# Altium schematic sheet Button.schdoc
size 297 x 209 mm; Symbol: Drawing-Symbol_A4; @Project Name: Hưhwwuey; @Page Count: 6; @Update Date: 2026-10-18; @Create Date: 2026-10-18; @Schematic Name: Schematic1; @Page No: 6; @Page Name: P1; Company: EasyEDA.com; Version: V1.0; Page Size: A4; Device: Drawing-Symbol_A4; @Create Time: 11:19:59; @Update Time: 11:19:59; Border: 1; Width: 1170; Height: 825; Region Start: 1; X Region Count: 6; Y Region Count: 4; Blade Width: 10; Title Block Position: 3; @Board Name: Board1
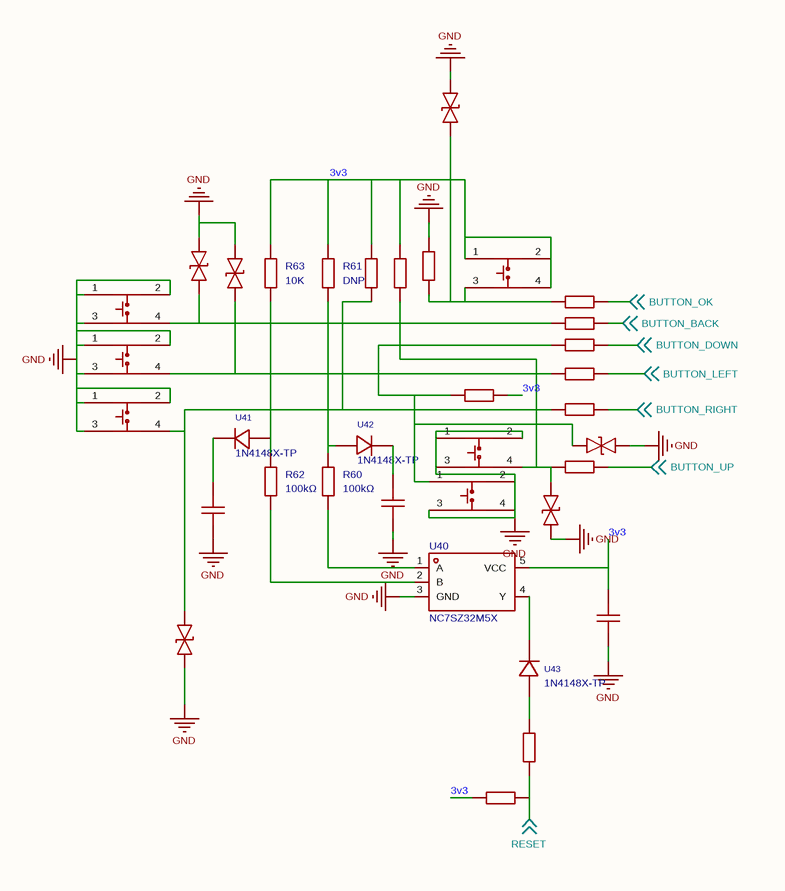
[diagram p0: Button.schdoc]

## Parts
C87  10uF  [C0603]  (value not drawn)
C88  10uF  [C0603]  (value not drawn)
C89  100nF  [C0402]  (value not drawn)
D9  ESD241B1W0201E6327XTSA1  [WLL-2-3_L0.6-W0.3-P0.36-BI]  (value not drawn)
D10  ESD241B1W0201E6327XTSA1  [WLL-2-3_L0.6-W0.3-P0.36-BI]  (value not drawn)
D11  ESD241B1W0201E6327XTSA1  [WLL-2-3_L0.6-W0.3-P0.36-BI]  (value not drawn)
D12  ESD241B1W0201E6327XTSA1  [WLL-2-3_L0.6-W0.3-P0.36-BI]  (value not drawn)
D13  ESD241B1W0201E6327XTSA1  [WLL-2-3_L0.6-W0.3-P0.36-BI]  (value not drawn)
D14  ESD241B1W0201E6327XTSA1  [WLL-2-3_L0.6-W0.3-P0.36-BI]  (value not drawn)
R60  100kΩ  [R0402]
R61  DNP  [R0402]
R62  100kΩ  [R0402]
R63  10K  [R0402]
R64  510Ω  [R0402]  (value not drawn)
R65  10K  [R0402]  (value not drawn)
R66  330Ω  [R0402]  (value not drawn)
R67  330Ω  [R0402]  (value not drawn)
R68  330Ω  [R0402]  (value not drawn)
R69  10K  [R0402]  (value not drawn)
R70  330Ω  [R0402]  (value not drawn)
R71  10K  [R0402]  (value not drawn)
R72  330Ω  [R0402]  (value not drawn)
R73  10K  [R0402]  (value not drawn)
R74  330Ω  [R0402]  (value not drawn)
R75  10K  [R0402]  (value not drawn)
SW1  SKRMAAE010  [SW-SMD_4P-L4.5-W4.5-P3.30-S3.75]  (value not drawn)
SW2  SKRMAAE010  [SW-SMD_4P-L4.5-W4.5-P3.30-S3.75]  (value not drawn)
SW3  SKRMAAE010  [SW-SMD_4P-L4.5-W4.5-P3.30-S3.75]  (value not drawn)
SW4  SKRMAAE010  [SW-SMD_4P-L4.5-W4.5-P3.30-S3.75]  (value not drawn)
SW5  SKRMAAE010  [SW-SMD_4P-L4.5-W4.5-P3.30-S3.75]  (value not drawn)
SW6  SKRMAAE010  [SW-SMD_4P-L4.5-W4.5-P3.30-S3.75]  (value not drawn)
U40  NC7SZ32M5X  [SOT-23-5_L2.9-W1.6-P0.95-LS2.8-BR]
U41  1N4148X-TP  [SOD-523F_L1.2-W0.8-LS1.7-RD]
U42  1N4148X-TP  [SOD-523F_L1.2-W0.8-LS1.7-RD]
U43  1N4148X-TP  [SOD-523F_L1.2-W0.8-LS1.7-RD]

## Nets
GND: C87.1 C88.1 C89.2 D9.2 D10.2 D11.1 D12.2 D13.1 D14.1 R71.2 SW1.1 SW1.2 SW1.3 SW2.1 SW2.2 SW2.3 SW3.1 SW3.2 SW3.3 SW5.1 SW5.2 SW5.3 SW6.2 SW6.3 SW6.4 U40.3(GND)
3v3: C89.1 R61.2 R63.2 R65.1 R69.2 R73.2 R75.2 SW4.1 SW4.2 SW4.4 U40.5(VCC)
BUTTON_BACK: R66.2 ; off-sheet BUTTON_BACK
BUTTON_DOWN: R74.2 ; off-sheet BUTTON_DOWN
BUTTON_LEFT: R67.2 ; off-sheet BUTTON_LEFT
BUTTON_OK: R70.2 ; off-sheet BUTTON_OK
BUTTON_RIGHT: R68.2 ; off-sheet BUTTON_RIGHT
BUTTON_UP: R72.2 ; off-sheet BUTTON_UP
RESET: R64.1 R65.2 ; off-sheet RESET
NetC87_2: C87.2 U41.1(C)
NetC88_2: C88.2 U42.1(C)
NetD9_1: D9.1 R60.2 R61.1 R66.1 SW1.4 U42.2(A)
NetD10_1: D10.1 R62.2 R63.1 R67.1 SW2.4 U41.2(A)
NetD11_2: D11.2 R68.1 R69.1 SW3.4
NetD12_1: D12.1 R70.1 R71.1 SW4.3
NetD13_2: D13.2 R72.1 R73.1 SW5.4
NetD14_2: D14.2 R74.1 R75.1 SW6.1
NetR60_1: R60.1 U40.1(A)
NetR62_1: R62.1 U40.2(B)
NetR64_2: R64.2 U43.2(A)
NetU40_4: U40.4(Y) U43.1(C)

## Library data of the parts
C87 C88 = CL10A106KP8NNNC: Capacitance:10uF Tolerance:±10% Tolerance:±10% Voltage Rating:10V Temperature Coefficient:X5R; Manufacturer: SAMSUNG(三星); 3D Model: 624118aa3cc7497086c383c2d72e08520819f05c4eef4c71ace90d822a990e87; 3D Model Transform: 62.992,31.496,0,0,0,0,0,0,0; Tolerance: ±10%; Voltage Rating: 10V; Temperature Coefficient: X5R; AddInBom: yes; ModelName: C0603_L1.6-W0.8-H0.8
C89 = CAP_0402: Symbol: CAP_OLD; 3D Model: b7d13df3e9464d7a99d0651d1a5b4d570819f05c4eef4c71ace90d822a990e87; 3D Model Transform: 39.37,19.685,0,0,0,0,0,0,0; ConvertToPcb: yes; ModelName: C0402_L1.0-W0.5-H0.5
D9-D14 = ESD241B1W0201E6327XTSA1: Polarity:Bidirectional Reverse Stand-Off Voltage (Vrwm):3.3V Clamping Voltage:6V Peak Pulse Current (Ipp):4.5A@8/20us Peak Pulse Power Dissipation (Ppp):25W Reverse Leakage Current (Ir):1nA Number of Channels:1 Operating Temperature:-55℃~+125℃ Operating T; Manufacturer: Infineon(英飞凌); AddInBom: yes; ModelId: cb6ec831a54246eaa6879a507ceff6700819f05c4eef4c71ace90d822a990e87; ModelTransform: 22.8346,11.0236,0,0,0,0,0,0,0; Reverse Stand-Off Voltage (Vrwm): 3.3V; Clamping Voltage: 6V; Peak Pulse Power Dissipation (Ppp): 25W; Reverse Leakage Current (Ir): 1nA; Number of Channels: 1; level of protection: IEC 61000-4-4；IEC 61000-4-5；IEC 61000-4-2; Type: TVS; Junction Capacitance: 6.5pF
R60 R62 = RC-02W104JT: Type:Thick Film Resistor Resistance:100kΩ Tolerance:±5% Tolerance:±5% Power(Watts):62.5mW Voltage-Supply(Max):50V Temperature Coefficient:±200ppm/℃ Temperature Coefficient:±200ppm/℃ Operating Temperature:-55℃~+155℃ Operating Temperature:-55℃~+155℃; Manufacturer: FH(风华); AddInBom: yes; ModelId: efdecb7dae4442949d28eecaf748420f0819f05c4eef4c71ace90d822a990e87; ModelName: R0402_L1.0-W0.5-H0.4; ModelTransform: 39.37,19.685,0,0,0,0,0,0,0; Tolerance: ±5%; Power(Watts): 62.5mW; Voltage-Supply(Max): 50V
R61 = Res_0402: Symbol: Res; 3D Model: efdecb7dae4442949d28eecaf748420f0819f05c4eef4c71ace90d822a990e87; 3D Model Transform: 39.37,19.685,0,0,0,0,0,0,0; Add into BOM: no; ConvertToPcb: yes; ModelName: R0402_L1.0-W0.5-H0.4
R63 R65 R69 R71 R73 R75 = Res_0402: Symbol: Res; 3D Model: efdecb7dae4442949d28eecaf748420f0819f05c4eef4c71ace90d822a990e87; 3D Model Transform: 39.37,19.685,0,0,0,0,0,0,0; ConvertToPcb: yes; ModelName: R0402_L1.0-W0.5-H0.4
R64 = RTT02511JTH: Type:Thick Film Resistor Resistance:510Ω Tolerance:±5% Tolerance:±5% Power(Watts):62.5mW Voltage-Supply(Max):50V Temperature Coefficient:±100ppm/℃ Temperature Coefficient:±100ppm/℃ Operating Temperature:-55℃~+155℃ Operating Temperature:-55℃~+155℃; Manufacturer: RALEC(旺诠); AddInBom: yes; ModelId: efdecb7dae4442949d28eecaf748420f0819f05c4eef4c71ace90d822a990e87; ModelName: R0402_L1.0-W0.5-H0.4; ModelTransform: 39.37,19.685,0,0,0,0,0,0,0; Tolerance: ±5%; Power(Watts): 62.5mW; Voltage-Supply(Max): 50V
R66-R68 R70 R72 R74 = WR04X331JTL: Type:Thick Film Resistor Resistance:330Ω Tolerance:±5% Tolerance:±5% Power(Watts):62.5mW Voltage-Supply(Max):50V Temperature Coefficient:±100ppm/℃ Temperature Coefficient:±100ppm/℃ Operating Temperature:-55℃~+155℃ Operating Temperature:-55℃~+155℃; Manufacturer: Walsin(华新科); 3D Model: efdecb7dae4442949d28eecaf748420f0819f05c4eef4c71ace90d822a990e87; 3D Model Transform: 39.37,19.685,0,0,0,0,0,0,0; Tolerance: ±5%; Power(Watts): 62.5mW; Voltage-Supply(Max): 50V; AddInBom: yes; ModelName: R0402_L1.0-W0.5-H0.4
SW1-SW6 = SKRMAAE010: Circuit:SPST-NO Actuator Style:Round Button Operating Force:1.6N Mounting Type:Surface Mount,Vertical Length:4.5mm Width:4.5mm Switch Height:0.4mm Contact Current:50mA Voltage Rating:12V With Lamp:- Termination Style:J-Lead Life:500,000 cycles Operating T; Manufacturer: ALPSALPINE(阿尔卑斯阿尔派); AddInBom: yes; ModelId: a90a54b2682f47f9a023e3ba9d7e84000819f05c4eef4c71ace90d822a990e87; ModelTransform: 177.165,177.165,0,0,0,0,0.005,0,0; Operating Force: 1.6N; Switch Height: 0.4mm; Contact Current: 50mA; Voltage Rating: 12V
U40 = NC7SZ32M5X: Logic Type:OR Gate Number of Gates:1 Voltage - Supply:1.65V~5.5V Voltage - Supply:1.65V~5.5V Quiescent Current:2uA Current - Output Low(IOL):32mA Current - Output High(IOH):32mA Input Logic Level - High:- Input Logic Level - High:- Input Logic Level - Low; Manufacturer: onsemi(安森美); AddInBom: yes; ModelId: 5bf53fa97d9848eeb37d584d4730b7f10819f05c4eef4c71ace90d822a990e87; ModelTransform: 114.173,114.173,0,90,0,0,0,0,0; Logic Type: OR Gate; Number of Gates: 1; Quiescent Current: 2uA; Current - Output Low(IOL): 32mA; Output Logic Level - High: 1.55V；2.9V；4.4V；1.7V；2.2V; Output Logic Level - Low: 100mV; Propagation Delay: 4.5ns@5V,50pF; Inputs per Gates: 2
U41 = 1N4148X-TP: Diode Configuration:1 Independent Pd - Power Dissipation:200mW Current - Rectified:150mA Voltage - DC Reverse(Vr):75V Voltage - Forward(Vf@If):1.25V@150mA Non-Repetitive Peak Forward Surge Current:2A Reverse Leakage Current (Ir):1uA@75V Reverse Recovery T; Manufacturer: MCC(美微科); AddInBom: yes; ModelId: 53f385f253c24b16903baed56d7fb4c80819f05c4eef4c71ace90d822a990e87; ModelName: SOD-523F_L1.2-W0.8-H0.6-LS1.6; ModelTransform: 62.992,31.496,0,0,0,0,-0.005,0.16,0; Pd - Power Dissipation: 200mW; Current - Rectified: 150mA; Voltage - DC Reverse(Vr): 75V; Non-Repetitive Peak Forward Surge Current: 2A; Reverse Recovery Time (trr): 4ns; Operating Junction Temperature Range: -65℃~+150℃
U42 U43 = 1N4148X-TP: Diode Configuration:1 Independent Pd - Power Dissipation:200mW Current - Rectified:150mA Voltage - DC Reverse(Vr):75V Voltage - Forward(Vf@If):1.25V@150mA Non-Repetitive Peak Forward Surge Current:2A Reverse Leakage Current (Ir):1uA@75V Reverse Recovery T; Manufacturer: MCC(美微科); 3D Model: 53f385f253c24b16903baed56d7fb4c80819f05c4eef4c71ace90d822a990e87; 3D Model Transform: 62.992,31.496,0,0,0,0,-0.005,0.16,0; Pd - Power Dissipation: 200mW; Current - Rectified: 150mA; Voltage - DC Reverse(Vr): 75V; Non-Repetitive Peak Forward Surge Current: 2A; Reverse Recovery Time (trr): 4ns; Operating Junction Temperature Range: -65℃~+150℃; AddInBom: yes; ModelName: SOD-523F_L1.2-W0.8-H0.6-LS1.6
